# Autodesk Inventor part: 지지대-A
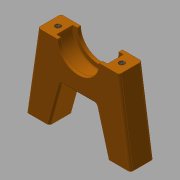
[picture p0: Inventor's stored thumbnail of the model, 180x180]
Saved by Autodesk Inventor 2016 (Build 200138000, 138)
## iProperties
Created: 2018-01
Part Number: 지지대-A
Material: 일반
Document SubType Name: Modeling
Designer: mduedu
Density: 1 g/cm^3
Appearance: 주황색
Author: mduedu
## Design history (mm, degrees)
sketch "스케치1"
  geometry: L1 (-22.5, 0)-(22.5, 0); L2 (22.5, 0)-(17.5, 34); L3 (17.5, 34)-(-17.5, 34); L4 (-17.5, 34)-(-22.5, 0); 3 further points
  constraints: 8 end point, 2 midpoint, 1 coincident, 1 horizontal, 1 parallel, 1 vertical alignment
  dimensions: "d0" = 45 distance of L1.start L1.end; "d3" = 35 distance of L2.end L3.end; "d4" = 34 vertical distance of L1.end L2.end
extrude "돌출1" new body sketch "스케치1" stored distance "d5" = 10; taper "d6" = 0 deg
sketch "스케치2"
  geometry: L1 (-12.5, 0)-(12.5, 0); L2 (12.5, 0)-(7.5, 18); L3 (7.5, 18)-(-7.5, 18); L4 (-7.5, 18)-(-12.5, 0); L5 (-22.5, 0)-(22.5, 0) reference; 4 further points
  constraints: 8 end point, 4 midpoint, 1 horizontal, 1 parallel, 1 vertical alignment
  dimensions: "d7" = 10 distance of L1.start L5.start; "d8" = 10 distance of L1.end L5.end (derived); "d9" = 15 distance of L2.end L3.end; "d10" = 18 distance between parallel lines of L1 L3
extrude "돌출2" cut sketch "스케치2" stored distance "d11" = 10; taper "d12" = 0 deg
sketch "스케치3"
  geometry: L1 (-17.5, 34)-(17.5, 34) reference; C1 r 11 at (0, 34); C2 r 9 at (0, 34); 1 further point
  constraints: 2 centre point, 1 coincident, 1 midpoint
  dimensions: "d13" = 22 diameter of C1; "d16" = 18 diameter of C2
extrude "돌출3" cut sketch "스케치3" stored distance "d14" = 7; taper "d15" = 0 deg
extrude "돌출4" cut sketch "스케치3" stored distance "d17" = 7; taper "d18" = 0 deg
fillet "모깎기1" dims "d19" = 0.3
fillet "모깎기2" dims "d20" = 1
fillet "모깎기3" dims "d21" = 1
fillet "모깎기4" dims "d22" = 1
sketch "스케치4"
  geometry: 2 further points
  constraints: 2 other
hole "구멍1" sketch "스케치4" at (-22.771, -3.5), (4.771, -3.5) diameter "d23" = 2.459; stored, may be unused: countersink angle "d27" = 90 deg, drill point angle "d29" = 120 deg; dims "d24" = 4.5, "d25" = 4, "d26" = 2, "d28" = 6
sketch "스케치5"
  geometry: 4 further points
  constraints: 4 other
hole "구멍2" sketch "스케치5" at (40, 4), (5, -27), (40, -27), (5, 4) diameter "d30" = 2.459; stored, may be unused: countersink angle "d34" = 90 deg, drill point angle "d36" = 120 deg; dims "d31" = 6.9, "d32" = 4, "d33" = 2, "d35" = 8.4
node "솔리드1"
